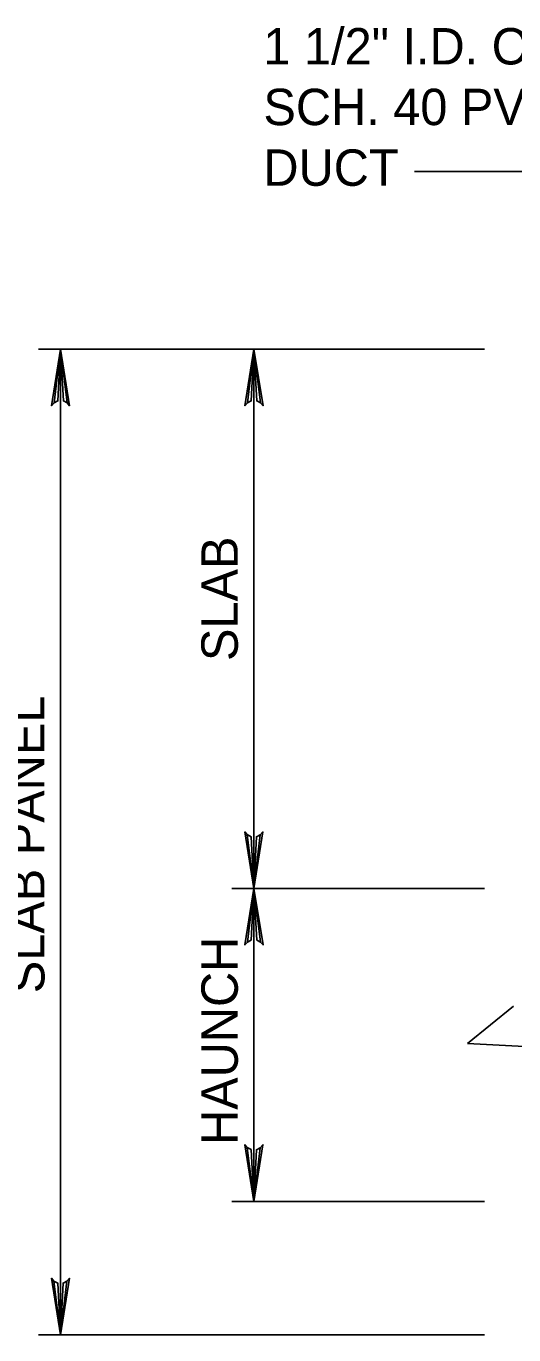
# Model space of a CAD drawing. Extents: x 641328 to 643024, y 298283 to 300065.
# Drawn here: x 642544.1 to 642584.3, y 299659.4 to 299767.3 of the extents above; entities that cross this region are included whole.
import ezdxf

# ---------------------------------------------------------------- set-up
doc = ezdxf.new("R2010")
doc.units = 0
doc.layers.add('2', color=7, linetype='Continuous')
doc.layers.add('63', color=7, linetype='Continuous')

msp = doc.modelspace()

# ---------------------------------------------------------------- linework, layer by layer
at = {"layer": '2'}
for p, q in [((642593.54, 299755.27), (642576.09, 299755.27)), ((642581.86, 299740.64), (642545.1, 299740.64)), ((642581.86, 299696.2), (642561.03, 299696.2)), ((642581.86, 299670.41), (642561.03, 299670.41)), ((642581.86, 299659.41), (642545.1, 299659.41))]:
    msp.add_line(p, q, dxfattribs=at)
at = {"layer": '63'}
for p, q in [((642546.92, 299740.64), (642546.92, 299659.41)), ((642562.86, 299740.64), (642562.86, 299696.2)), ((642562.86, 299696.2), (642562.86, 299670.41)), ((642580.45, 299683.43), (642584.25, 299686.5)), ((642588.48, 299683), (642580.45, 299683.43))]:
    msp.add_line(p, q, dxfattribs=at)
for points in [[(642547.48, 299736.21), (642547.16, 299736.38), (642546.92, 299740.64), (642547.48, 299736.21), (642547.67, 299735.98), (642546.92, 299740.64), (642546.71, 299736.38), (642546.4, 299736.22), (642546.92, 299740.64), (642546.18, 299735.98), (642546.4, 299736.22)], [(642563.41, 299736.21), (642563.09, 299736.38), (642562.86, 299740.64), (642563.41, 299736.21), (642563.61, 299735.98), (642562.86, 299740.64), (642562.64, 299736.38), (642562.33, 299736.22), (642562.86, 299740.64), (642562.12, 299735.98), (642562.33, 299736.22)], [(642562.3, 299700.63), (642562.62, 299700.46), (642562.86, 299696.2), (642562.3, 299700.63), (642562.11, 299700.86), (642562.86, 299696.2), (642563.07, 299700.46), (642563.38, 299700.62), (642562.86, 299696.2), (642563.6, 299700.86), (642563.38, 299700.62)], [(642563.41, 299691.77), (642563.09, 299691.94), (642562.86, 299696.2), (642563.41, 299691.77), (642563.61, 299691.54), (642562.86, 299696.2), (642562.64, 299691.94), (642562.33, 299691.78), (642562.86, 299696.2), (642562.12, 299691.54), (642562.33, 299691.78)], [(642562.3, 299674.84), (642562.62, 299674.68), (642562.86, 299670.41), (642562.3, 299674.84), (642562.11, 299675.07), (642562.86, 299670.41), (642563.07, 299674.67), (642563.38, 299674.83), (642562.86, 299670.41), (642563.6, 299675.07), (642563.38, 299674.83)], [(642546.37, 299663.84), (642546.69, 299663.68), (642546.92, 299659.41), (642546.37, 299663.84), (642546.17, 299664.07), (642546.92, 299659.41), (642547.13, 299663.67), (642547.45, 299663.83), (642546.92, 299659.41), (642547.66, 299664.07), (642547.45, 299663.83)]]:
    msp.add_lwpolyline(points, dxfattribs=at)

# ---------------------------------------------------------------- texts
at = {"layer": '2'}
for s, p in [('1 1/2" I.D. OR 2" I.D.', (642563.64, 299764.1)), ('SCH. 40 PVC POST-TENSIONING', (642563.64, 299759.1)), ('DUCT', (642563.64, 299754.1))]:
    msp.add_text(s, height=3, dxfattribs=at).set_placement(p)
at = {"layer": '63'}
for s, p in [('SLAB', (642561.53, 299714.94)), ('SLAB PANEL', (642545.6, 299687.56)), ('HAUNCH', (642561.53, 299675.06))]:
    msp.add_text(s, height=3, rotation=90, dxfattribs=at).set_placement(p)

doc.saveas('drawing.dxf')
